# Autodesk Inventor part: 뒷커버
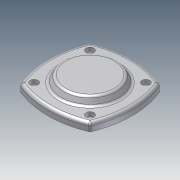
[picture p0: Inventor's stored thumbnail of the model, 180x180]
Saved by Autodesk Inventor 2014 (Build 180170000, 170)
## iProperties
Created: 2013-02
Part Number: 뒷커버
Document SubType Name: Modeling
Designer: 한국산업디자인학원[gmhk.co.kr]
Density: 1 g/cm^3
Material: 일반
Appearance: 기본값
Mass: 83.2003 g
Surface Area: 194.999 cm^2
Volume: 83.2003 cm^3
Author: 한국산업디자인학원[gmhk.co.kr]
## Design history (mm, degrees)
sketch "스케치1"
  geometry: C1 r 30 at (0, 0) reference; A1 r 91.05 centre (0, -48.55) between (34.185, 35.839) and (-34.185, 35.839) reference; A2 r 91.05 centre (48.55, 0) between (-35.839, 34.185) and (-35.839, -34.185) reference; A3 r 3 centre (-33.058, 33.058) between (-34.185, 35.839) and (-35.839, 34.185) reference; A4 r 3 centre (33.058, 33.058) between (35.839, 34.185) and (34.185, 35.839) reference; A5 r 91.05 centre (-48.55, 0) between (35.839, -34.185) and (35.839, 34.185) reference; A6 r 3 centre (33.058, -33.058) between (34.185, -35.839) and (35.839, -34.185) reference; A7 r 91.05 centre (0, 48.55) between (-34.185, -35.839) and (34.185, -35.839) reference; A8 r 3 centre (-33.058, -33.058) between (-35.839, -34.185) and (-34.185, -35.839) reference; 1 further point
  node "참조1"
  node "참조2"
  node "참조3"
  node "참조4"
  node "참조5"
  node "참조6"
  node "참조7"
  node "참조8"
  node "참조9"
extrude "돌출1" new body sketch "스케치1" distance "d0" = 8; taper "d1" = 0 deg
sketch "스케치2"
  geometry: C1 r 30 at (0, 0); 1 further point
  constraints: 1 centre point, 1 coincident
  dimensions: "d2" = 60 diameter of C1
extrude "돌출2" join sketch "스케치2" distance "d3" = 7; taper "d4" = -30 deg
sketch "스케치3"
  geometry: C1 r 1.621 at (28.284, 28.284) reference; C2 r 1.621 at (-28.284, 28.284) reference; C3 r 1.621 at (-28.284, -28.284) reference; C4 r 1.621 at (28.284, -28.284) reference; 1 further point
hole "구멍2" sketch "스케치3" at (28.284, 28.284), (28.284, -28.284), (-28.284, -28.284), (-28.284, 28.284) diameter "d14" = 4.5; stored, may be unused: countersink angle "d18" = 90 deg, drill point angle "d20" = 118 deg; dims "d15" = 6, "d16" = 8, "d17" = 4.4, "d19" = 20
extrude "돌출3" join sketch "스케치1" distance "d21" = 12; taper "d22" = 0 deg
hole "구멍3" diameter "d25" = 30; stored, may be unused: countersink angle "d29" = 90 deg, drill point angle "d31" = 0 deg; dims "d23" = 10, "d24" = 10, "d26" = 6, "d27" = 40, "d28" = 12, "d30" = 15
fillet "모깎기1" dims "d32" = 3, "d33" = 0.3
chamfer "모따기1" distance "d34" = 1; stored, may be unused: second distance "d35" = 2, angle "d36" = 45 deg
node "솔리드1"
node "참조10"
node "참조11"
node "참조12"
node "참조13"
